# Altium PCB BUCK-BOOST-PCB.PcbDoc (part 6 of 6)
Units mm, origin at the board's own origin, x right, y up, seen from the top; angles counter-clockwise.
Board outline 99.9 x 67.48 mm, 4 copper layers (Top Layer, POWER, GND, Bottom Layer); 181 components, 110 nets, 560 pads, 389 vias.
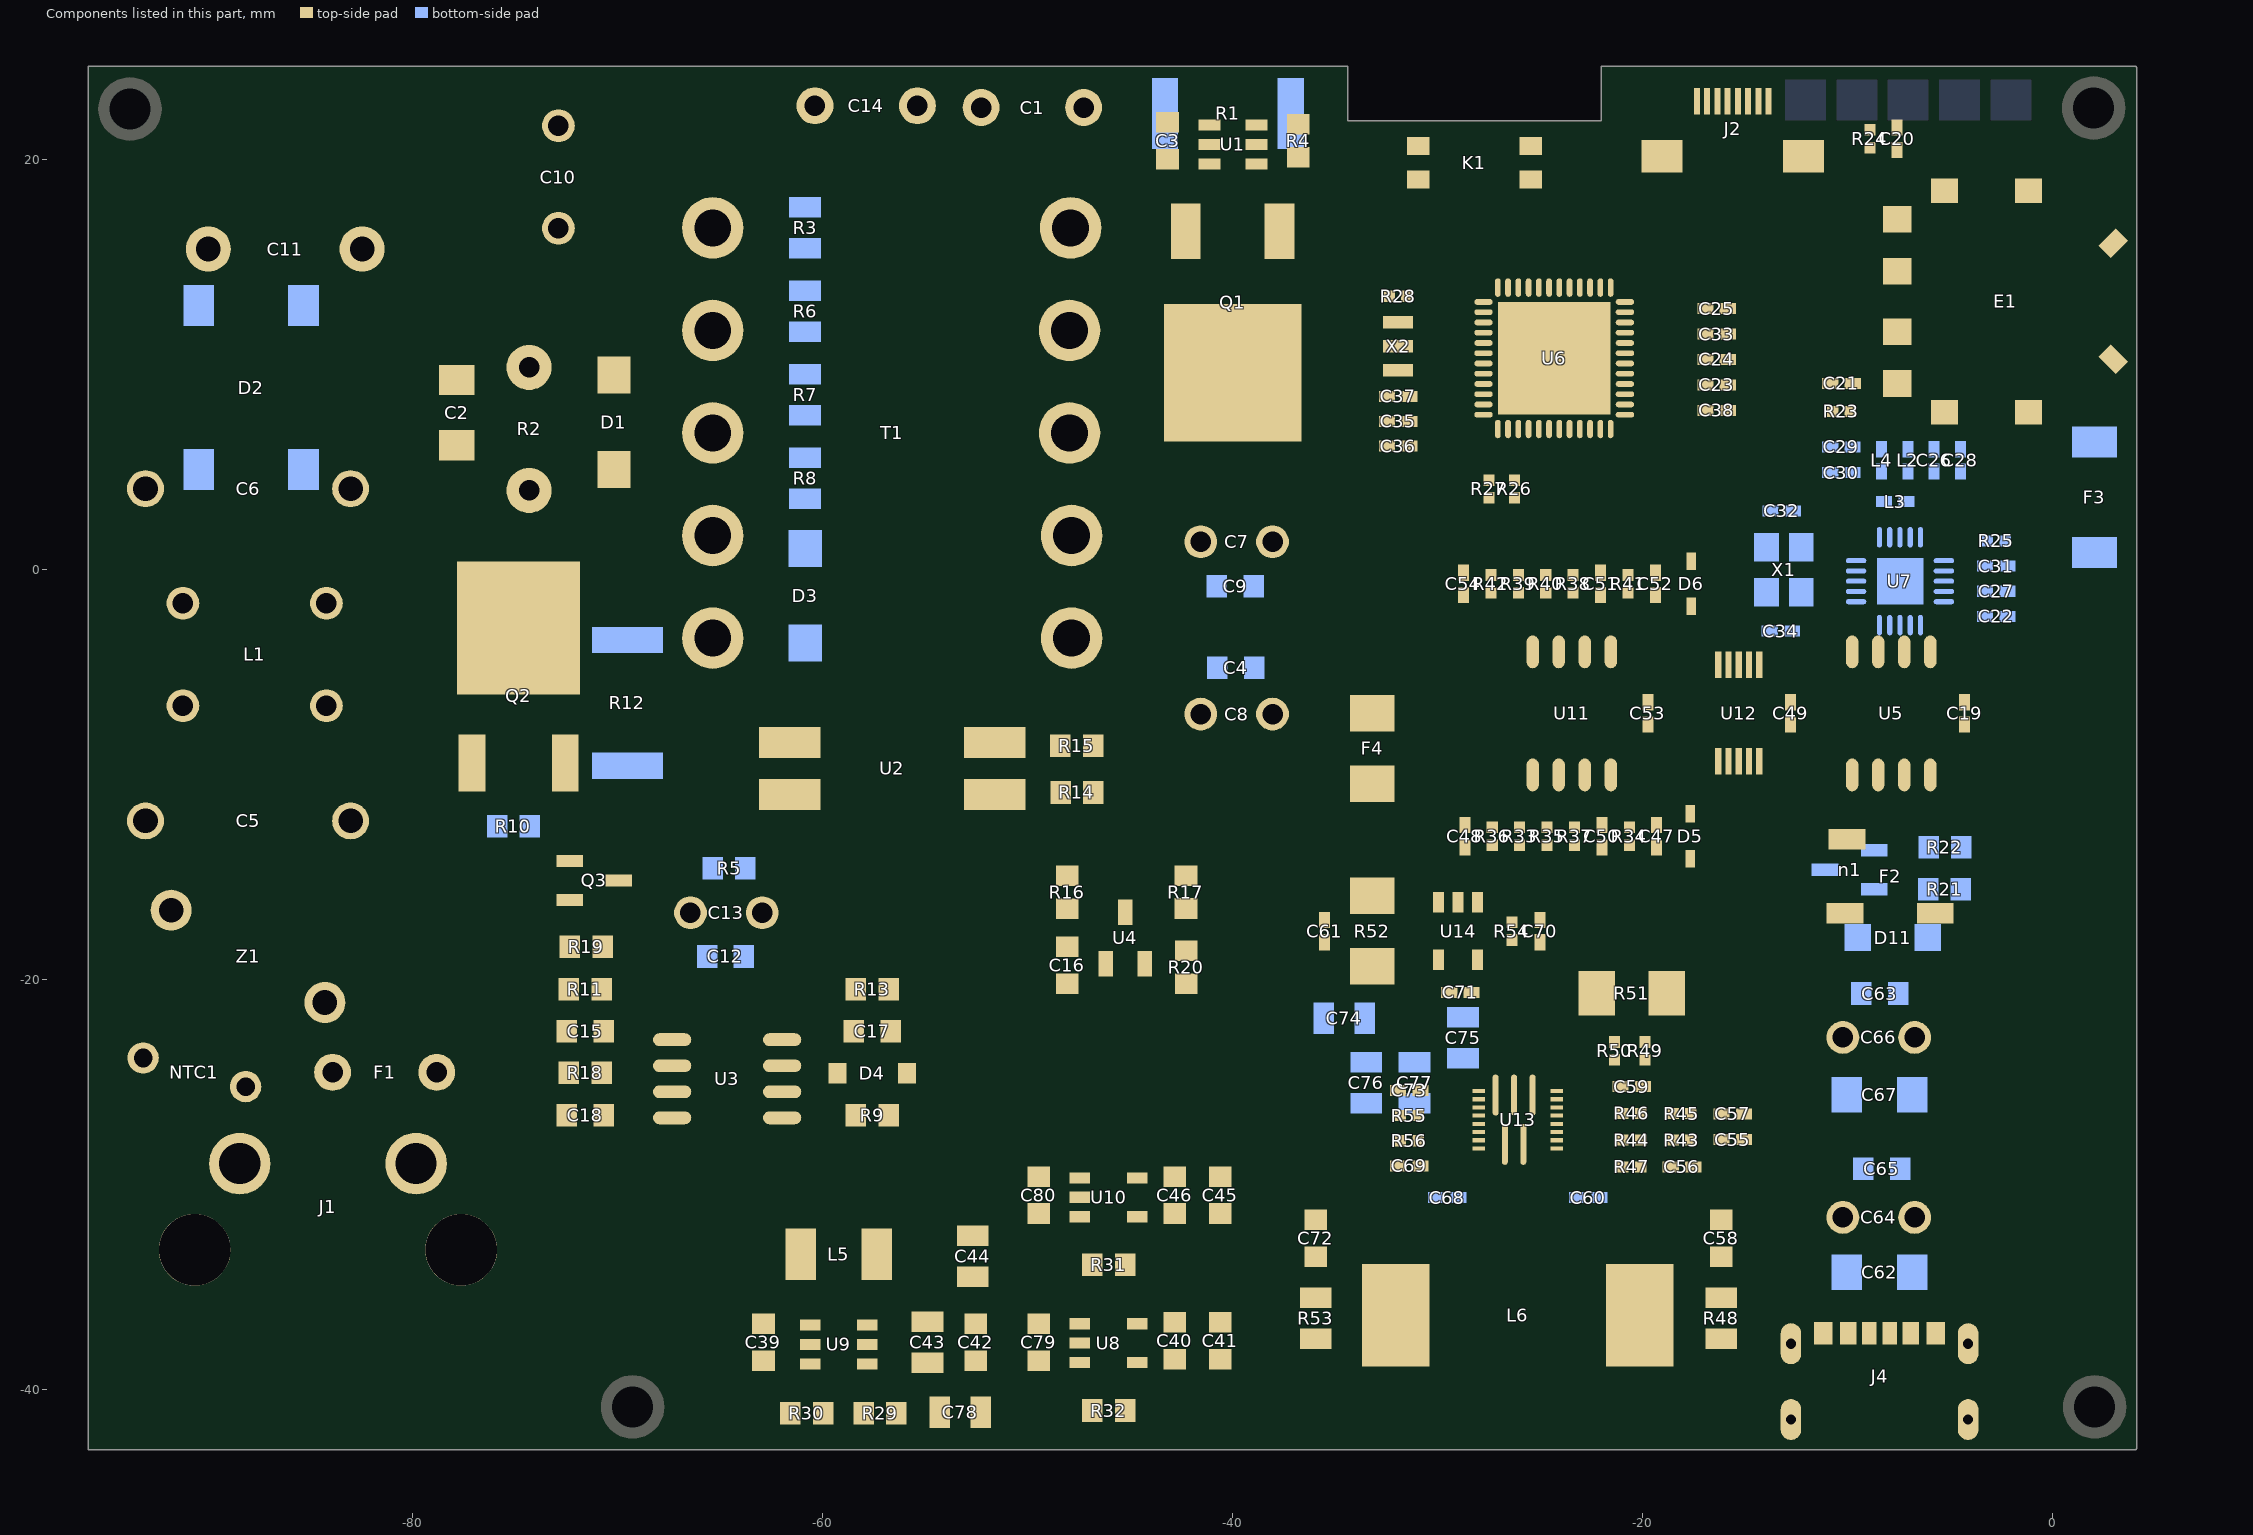
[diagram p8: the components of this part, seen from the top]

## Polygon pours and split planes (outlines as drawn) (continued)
NetC2_2 on Top Layer "Top Layer-No Net" (solid, remove dead copper, pour order 49): -91.314,13.969 -91.294,13.948 -88.834,13.948 -88.834,13.96 -88.445,14.349 -88.457,14.36 -88.457,16.068 -88.457,18.74 -86.504,20.693 -86.418,20.608 -67.908,20.608 -67.878,20.608 -67.509,20.24 -67.436,20.166 -67.436,15.516 -67.436,15.345 -67.104,15.014 -66.816,14.726 -65.596,14.726 -64.077,14.726 -63.699,15.103 -63.51,15.292 -63.51,16.268 -63.51,19.552 -66.637,22.678 -69.657,22.678 -87.652,22.678 -90.865,19.465 -91.321,19.009 -91.321,13.941
NetC6_2 on Top Layer "Top Layer-No Net" (solid, remove dead copper, pour order 43): -91.531,5.4 -91.556,5.376 -93.692,5.376 -93.85,5.376 -94.399,4.827 -94.48,4.746 -94.48,2.489 -94.48,2.164 -93.782,1.466 -93.04,0.724 -93.04,-1.394 -93.04,-2.427 -92.775,-2.692 -92.686,-2.781 -91.322,-2.781 -90.667,-2.781 -90.289,-2.404 -90.256,-2.371 -90.256,-0.452 -90.256,2.388 -91.255,3.386 -91.446,3.578 -91.446,4.791 -91.446,5.01 -91.817,5.381
NetC6_1 on Top Layer "Top Layer-No Net" (solid, remove dead copper, pour order 44): -84.153,5.404 -84.129,5.38 -81.992,5.38 -81.834,5.38 -81.285,4.831 -81.204,4.75 -81.204,2.493 -81.204,2.168 -81.902,1.469 -82.644,0.728 -82.644,-1.391 -82.644,-2.423 -82.909,-2.689 -82.998,-2.777 -84.362,-2.777 -85.018,-2.777 -85.395,-2.4 -85.428,-2.367 -85.428,-0.448 -85.428,2.391 -84.43,3.39 -84.238,3.581 -84.238,4.794 -84.238,5.014 -83.867,5.385
NetC5_2 on Top Layer "Top Layer-No Net" (solid, remove dead copper, pour order 42): -85.193,-5.218 -83.228,-5.218 -82.795,-5.651 -82.756,-5.691 -82.756,-8.363 -82.756,-10.132 -81.99,-10.898 -81.733,-11.154 -81.733,-12.41 -81.733,-13.941 -82.321,-14.529 -82.65,-14.858 -82.65,-20.449 -85.568,-20.449 -85.701,-20.316 -85.193,-19.808 -85.193,-5.359 -85.193,-5.357 -85.057,-5.221
NetC5_1 on Top Layer "Top Layer-No Net" (solid, remove dead copper, pour order 37): -92.838,-5.262 -90.152,-5.262 -90.103,-5.262 -89.652,-5.712 -89.534,-5.83 -89.534,-8.091 -89.534,-9.351 -90.603,-10.42 -90.698,-10.516 -90.698,-13.631 -90.698,-15.058 -89.962,-15.795 -89.938,-15.819 -89.938,-18.148 -89.938,-19.599 -90.698,-20.359 -91.317,-20.978 -91.317,-22.88 -91.317,-24.691 -91.582,-24.957 -91.951,-25.325 -93.096,-25.325 -94.155,-25.325 -94.371,-25.109 -94.522,-24.958 -94.522,-20.504 -94.522,-6.43 -93.473,-5.381 -93.362,-5.269 -92.81,-5.269
NetC5_2 on Top Layer "Top Layer-No Net" (solid, remove dead copper, pour order 35): -85.2,-19.816 -83.334,-19.816 -83.284,-19.816 -82.711,-20.389 -82.65,-20.449 -82.65,-23.293 -82.65,-25.281 -82.798,-25.428 -83.067,-25.697 -83.651,-25.697 -84.761,-25.697 -85.042,-25.416 -85.225,-25.234 -85.225,-23.61 -85.225,-22.318 -85.494,-22.048 -85.701,-21.841 -85.701,-20.938 -85.701,-20.316 -85.185,-19.8
NetF1_2 on Top Layer "Top Layer-No Net" (solid, remove dead copper, pour order 34): -80.585,-23.332 -78.318,-23.332 -77.732,-23.919 -77.437,-24.214 -77.437,-27.935 -77.437,-29.943 -77.983,-30.489 -78.115,-30.621 -79.445,-30.621 -81.305,-30.621 -81.674,-30.253 -81.747,-30.179 -81.747,-26.857 -81.747,-26.797 -80.951,-26.001 -80.555,-25.604 -80.555,-24.004 -80.555,-23.83 -80.057,-23.332
NetJ1_2 on Top Layer "Top Layer-No Net" (solid, remove dead copper, pour order 33): -89.044,-24.096 -87.324,-24.096 -86.98,-24.44 -86.57,-24.85 -86.57,-28.943 -86.57,-30.098 -86.879,-30.408 -87.168,-30.696 -87.479,-30.696 -89.764,-30.696 -90.019,-30.441 -90.218,-30.241 -90.218,-29.309 -90.218,-24.858 -89.473,-24.112 -89.447,-24.087 -89.033,-24.087
NetC68_1 on Top Layer "Top Layer-No Net" (solid, remove dead copper, pour order 57): -27.285,-27.069 -27.285,-27.066 -26.339,-27.066 -26.265,-27.066 -26.265,-27.35 -26.265,-38.704 -28.251,-38.704 -32.906,-38.704 -32.906,-36.574 -32.906,-34.923 -32.009,-34.923 -28.151,-34.923 -28.151,-32.621 -28.151,-30.009 -27.474,-30.009 -27.287,-30.009 -27.287,-27.065
NetC60_1 on Top Layer "Top Layer-No Net" (solid, remove dead copper, pour order 56): -25.081,-27.06 -25.081,-27.057 -26.027,-27.057 -26.101,-27.057 -26.101,-27.343 -26.101,-38.739 -24.115,-38.739 -19.46,-38.739 -19.46,-36.601 -19.46,-34.943 -20.357,-34.943 -24.215,-34.943 -24.215,-32.633 -24.215,-30.011 -24.892,-30.011 -25.079,-30.011 -25.079,-27.056
VIN on Top Layer "Top Layer-No Net" (solid, remove dead copper, pour order 58): -35.414,-10.226 -35.4,-10.212 -31.195,-10.212 -31.068,-10.212 -31.068,-15.63 -31.068,-15.912 -35.019,-15.912 -35.408,-15.912 -35.408,-10.206
12V on Top Layer "Top Layer-No Net" (solid, remove dead copper, pour order 59): -39.727,7.694 -39.727,-8.026 -34.107,-8.026 -31.632,-8.026 -31.632,-5.79 -31.632,-5.09 -35.832,-5.09 -36.637,-5.09 -36.637,7.718 -36.637,7.686 -39.67,7.686
DGND on Bottom Layer "Top Layer-No Net" (solid, remove dead copper, pour order 41): -46.017,-42.868 -46.017,-27.678 -37.668,-27.678 -34.533,-27.678 -34.533,4.796 -34.533,24.892 -30.819,24.892 6.487,24.892 6.487,21.709 6.487,-46.185 1.654,-46.185 -45.983,-46.185 -45.983,-42.822
PGND on Bottom Layer "Top Layer-No Net" (solid, remove dead copper, pour order 48): -84.779,17.198 -84.765,17.212 -81.571,17.212 -81.53,17.212 -81.222,16.904 -81.101,16.783 -81.101,15.265 -81.101,12.018 -81.45,11.669 -81.665,11.454 -82.323,11.454 -86.003,11.454 -86.283,11.734 -86.389,11.84 -86.389,13.91 -86.389,14.46 -85.905,14.944 -85.893,14.957 -84.322,14.957 -84.295,14.957 -83.986,15.265 -83.866,15.386 -83.866,16.822 -83.866,16.991 -83.643,17.214
NetC2_2 on Bottom Layer "Top Layer-No Net" (solid, remove dead copper, pour order 47): -91.784,17.118 -91.758,17.145 -88.913,17.145 -88.711,17.145 -88.482,16.916 -88.469,16.904 -88.469,15.427 -88.469,11.816 -88.643,11.642 -88.805,11.481 -89.328,11.481 -91.314,11.481 -91.516,11.683 -91.744,11.91 -91.744,12.407 -91.744,16.773 -91.396,17.121
NetC6_2 on Bottom Layer "Top Layer-No Net" (solid, remove dead copper, pour order 45): -89.42,6.091 -89.429,6.1 -93.28,6.1 -93.566,6.1 -93.812,5.854 -93.94,5.725 -93.94,4.552 -93.94,3.222 -93.638,2.92 -93.519,2.8 -92.391,2.8 -89.751,2.8 -89.485,3.066 -89.338,3.213 -89.338,4.789 -89.338,5.871 -89.564,6.097
NetC6_1 on Bottom Layer "Top Layer-No Net" (solid, remove dead copper, pour order 46): -86.28,6.091 -86.271,6.1 -82.42,6.1 -82.135,6.1 -81.888,5.854 -81.76,5.725 -81.76,4.552 -81.76,3.222 -82.062,2.92 -82.182,2.8 -83.309,2.8 -85.95,2.8 -86.215,3.066 -86.363,3.213 -86.363,4.789 -86.363,5.871 -86.136,6.097
PGND on Bottom Layer "Top Layer-No Net" (solid, remove dead copper, pour order 31): -71.702,-1.238 -71.702,-1.251 -64.105,-1.251 -63.528,-1.251 -63.528,-2.311 -63.528,-5.225 -65.312,-5.225 -71.702,-5.225 -71.702,-1.238
NetQ2_3 on Bottom Layer "Top Layer-No Net" (solid, remove dead copper, pour order 39): -71.669,-9.121 -71.669,-9.112 -67.596,-9.112 -67.211,-9.112 -67.211,-9.791 -67.211,-11.186 -67.832,-11.186 -71.669,-11.186 -71.669,-9.103
DGND on GND "Top Layer-No Net" (solid, remove dead copper, pour order 40): -46.017,-42.868 -46.017,-27.678 -37.668,-27.678 -34.533,-27.678 -34.533,4.796 -34.533,24.892 -30.819,24.892 6.487,24.892 6.487,21.709 6.487,-46.185 1.654,-46.185 -45.983,-46.185 -45.983,-42.822
GND on GND "Top Layer-No Net" (solid, remove dead copper, pour order 38): -40.251,3.534 -40.251,3.529 -50.474,3.529 -50.709,3.529 -50.709,3.358 -50.709,2.866 -40.197,2.866 -40.251,2.866 -40.251,3.358
GND on GND "Top Layer-No Net" (solid, remove dead copper, pour order 36): -63.363,-42.846 -63.363,-32.889 -49.42,-32.889 -48.924,-32.889 -48.924,-28.406 -48.924,-27.436 -40.434,-27.436 -37.419,-27.436 -37.419,-8.531 -37.419,-8.547 -43.823,-8.547 -45.032,-8.547 -45.032,-6.787 -45.032,-6.603 -49.018,-6.603 -50.709,-6.603 -50.709,-4.167 -50.709,3.358 -47.915,3.358 -40.251,3.358 -40.251,1.764 -40.251,3.534 -37.548,3.534 -35.229,3.534 -35.229,-4.3 -35.229,-5.478 -27.978,-5.478 -27.936,-5.478 -27.936,-12.438 -27.936,-15.765 -20.975,-15.765 5.716,-15.765 5.716,-20.657 5.716,-44.849 -0.403,-44.849 -63.4,-44.849 -63.4,-42.851

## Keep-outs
Keep-Out Layer:
  lines w0.1: -95.749,-42.868 -95.749,24.512 ; -95.748,-42.866 4.053,-42.866 ; -95.748,24.511 -34.418,24.511 -34.418,21.846 -21.951,21.846 -21.951,24.511 4.051,24.511 ; 4.053,-42.868 4.053,24.512
  lines w0.2: 0,-28.491 0,-8.491 1,-8.491 1,-28.491 0,-28.491
  lines w0.8: -61.514,-29.722 -52.572,-29.722 -52.572,-24.61 ; -57.277,-1.53 -57.277,2.831
  lines w1: -75.945,-25.923 -75.945,-21.562

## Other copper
Top Layer:
  rectangle net GND: -27.927,-22.036 -25.813,-21.459
  rectangle net GND: -27.927,-22.768 -26.212,-22.036
  rectangle net GND: -29.759,-22.768 -27.692,-21.458
GND:
  pour cut-out: -18.503,-15.276 -13.282,-15.276 -13.282,-15.474 -18.503,-15.474
  pour cut-out: -23.933,18.4 -23.933,14.832 -25.601,14.832 -25.601,18.4
  pour cut-out: -18.5,-15.484 -18.5,-18.974 -13.282,-18.974 -13.282,-15.474 -18.499,-15.474
  pour cut-out: 4.058,7.786 0.044,7.786 0.044,-0.425 4.058,-0.425
Bottom Layer:
  pour cut-out: -25.735,18.124 -25.121,18.124 -25.121,15.028 -25.731,15.028 -25.731,18.122
  pour cut-out: -8.637,-19.303 -8.627,-19.313 -5.108,-19.313 -5.108,-35.352 -8.621,-35.352 -8.621,-19.289
  pour cut-out: 4.058,7.786 0.044,7.786 0.044,-0.425 4.058,-0.425
  pour cut-out: -35.579,24.506 -34.418,24.506 -34.418,21.584 -35.568,21.584 -35.568,24.517

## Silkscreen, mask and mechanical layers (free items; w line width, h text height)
Top Overlay:
  lines w0.1: -48.194,-26.397 -48.194,-24.003 -47.769,-23.578 -41.713,-23.578 -41.246,-24.045 -41.246,-26.429 -41.614,-26.798 -47.793,-26.798 -48.194,-26.397
  lines w0.2: 0,-39.981 0,-36.981 ; 0,3 0,0 ; 4.065,6.268 4.065,19.946 ; 0,-36.981 1.104,-36.981 1.104,-8.491 1.104,0 0,0 ; 0,-36.981 0,0
  text "LWJ" at -47.562,-26.134 h3
Bottom Overlay:
  circle w0.2: c-3.07,-16.943 r0.297
  text "N" at -14.002,22.108 h1.52
Top Solder:
  lines w1: -52.701,-29.709 -52.572,-29.709
  lines w1.3: -69.604,-29.709 -69.604,-36.097 -66.129,-36.097 -66.129,-42.182 ; -69.599,-29.709 -52.572,-29.709 -52.572,-14.088 ; -57.264,23.693 -57.264,-7.598 -57.264,-14.006 -52.654,-14.006
Bottom Solder:
  lines w1.3: -69.604,-29.709 -69.604,-36.097 -66.129,-36.097 -66.129,-42.182 ; -69.599,-29.709 -52.572,-29.709 -52.572,-14.088 ; -57.264,23.693 -57.264,-7.598 -57.264,-14.006 -52.654,-14.006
